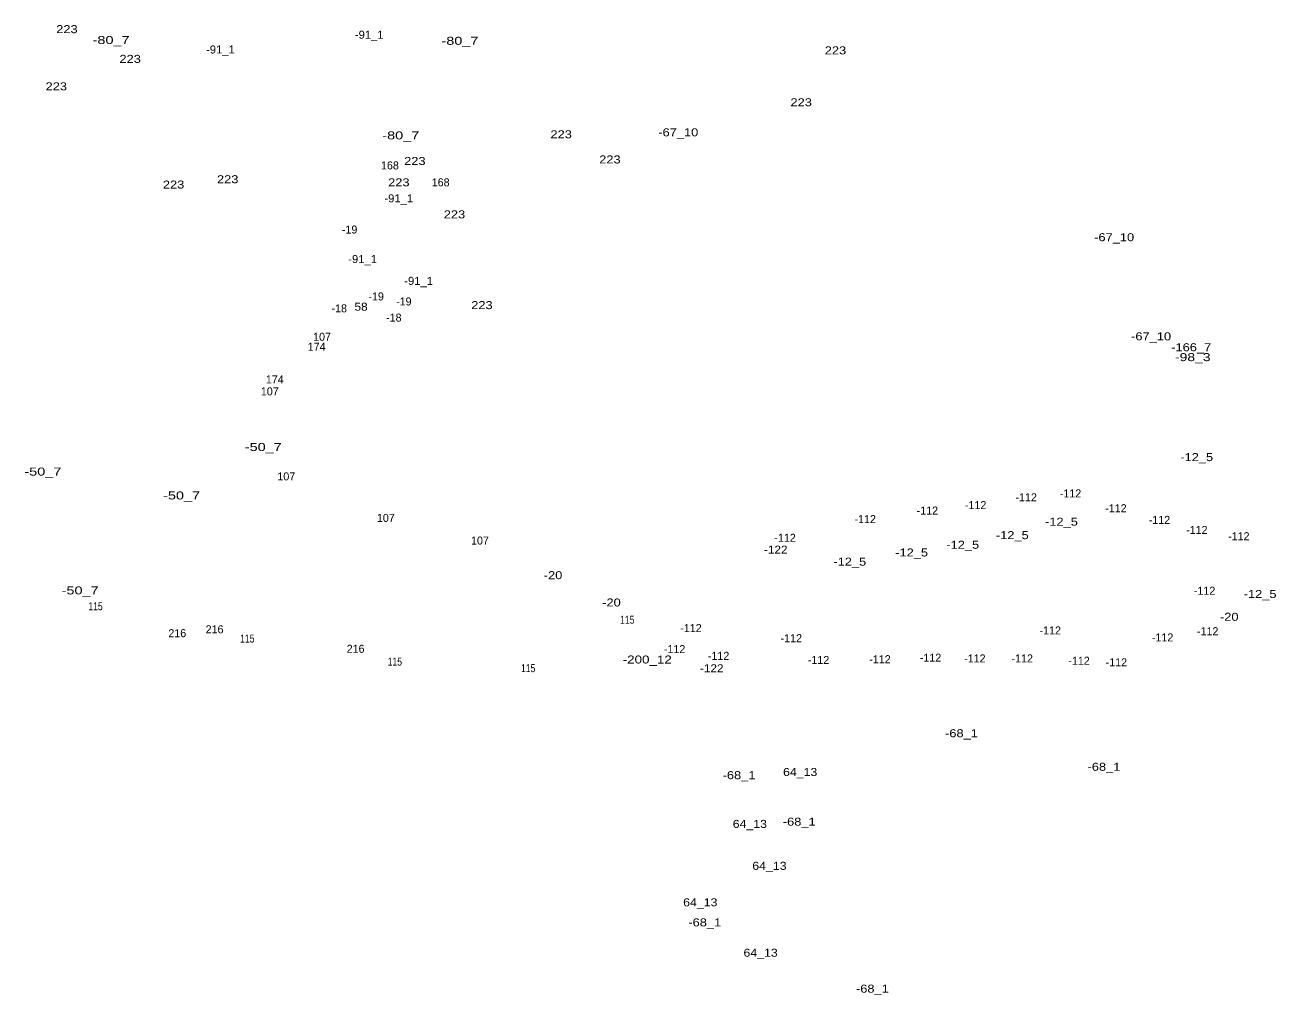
# Model space of a CAD drawing. Extents: x -662996 to -659766, y -998554 to -993949.
# Drawn here: x -662461 to -661836, y -995729 to -995245 of the extents above; entities that cross this region are included whole.
import ezdxf
from ezdxf.enums import TextEntityAlignment as Align

# ---------------------------------------------------------------- set-up
doc = ezdxf.new("R2010")
doc.units = 0
doc.header["$LTSCALE"] = 1.6
doc.layers.add('24', color=7, linetype='Continuous')

msp = doc.modelspace()

# ---------------------------------------------------------------- texts
at = {"layer": '24'}
for s, width, p in [('223', 1.2, (-662440.29, -995248.59)), ('-91_1', 1.05, (-662289.221, -995251.36)), ('-80_7', 1.35, (-662418.22, -995254.02)), ('-91_1', 1.05, (-662363.591, -995258.74)), ('-80_7', 1.35, (-662243.88, -995254.41)), ('223', 1.2, (-662056.199, -995259.2)), ('223', 1.2, (-662408.679, -995263.44)), ('223', 1.2, (-662445.62, -995277.16)), ('223', 1.2, (-662073.34, -995285.11)), ('-80_7', 1.35, (-662273.45, -995301.66)), ('223', 1.2, (-662193.299, -995301.11)), ('-67_10', 1.2, (-662134.77, -995300.13)), ('223', 1.2, (-662266.41, -995314.44)), ('223', 1.2, (-662168.929, -995313.68)), ('223', 1.2, (-662386.98, -995326.22)), ('223', 1.2, (-662359.939, -995323.56)), ('223', 1.2, (-662274.41, -995325.11)), ('-91_1', 1.05, (-662274.451, -995333.1)), ('223', 1.2, (-662246.61, -995341.11)), ('-67_10', 1.2, (-661916.94, -995352.52)), ('-91_1', 1.05, (-662292.52, -995363.43)), ('-91_1', 1.05, (-662264.541, -995374.32)), ('58', 1.1, (-662293.299, -995387.24)), ('223', 1.2, (-662232.9, -995386.44)), ('-67_10', 1.2, (-661898.47, -995402.04)), ('-166_7', 1.2, (-661878.429, -995407.48)), ('-98_3', 1.3, (-661877.65, -995412.42)), ('-50_7', 1.35, (-662342.16, -995457.31)), ('-12_5', 1.2, (-661875.679, -995462.36)), ('-50_7', 1.35, (-662452.32, -995469.6)), ('-50_7', 1.35, (-662383, -995481.51)), ('-12_5', 1.2, (-661943.27, -995494.63)), ('-12_5', 1.2, (-661967.84, -995501.35)), ('-122', 1.1, (-662086.061, -995508.59)), ('-12_5', 1.2, (-661992.61, -995506.15)), ('-12_5', 1.2, (-662049.059, -995514.6)), ('-12_5', 1.2, (-662018.15, -995510)), ('-20', 1.2, (-662197.34, -995521.34)), ('-50_7', 1.35, (-662433.69, -995528.95)), ('-12_5', 1.2, (-661844, -995530.74)), ('115', 0.8, (-662425.99, -995536.86)), ('-20', 1.2, (-662168.15, -995534.98)), ('115', 0.8, (-662160.25, -995543.58)), ('-20', 1.2, (-661859.41, -995542.14)), ('115', 0.8, (-662350.15, -995552.99)), ('115', 0.8, (-662276.41, -995564.52)), ('-200_12', 1.25, (-662150.27, -995563.47)), ('115', 0.8, (-662209.79, -995567.78)), ('-122', 1.1, (-662118.041, -995567.84)), ('-68_1', 1.2, (-661993.24, -995600.29)), ('-68_1', 1.2, (-662104.4, -995621.24)), ('64_13', 1.15, (-662073.85, -995619.66)), ('-68_1', 1.2, (-661922.03, -995617.05)), ('64_13', 1.15, (-662099, -995645.59)), ('-68_1', 1.2, (-662074.321, -995644.48)), ('64_13', 1.15, (-662089.209, -995666.53)), ('64_13', 1.15, (-662123.77, -995684.77)), ('-68_1', 1.2, (-662121.541, -995694.77)), ('64_13', 1.15, (-662093.62, -995709.94)), ('-68_1', 1.2, (-662037.76, -995727.88))]:
    msp.add_text(s, height=4, dxfattribs=dict(at, width=width)).set_placement(p, align=Align.CENTER)
for s, p in [('168', (-662278.861, -995316.66)), ('168', (-662253.51, -995325.11)), ('-19', (-662299.01, -995348.68)), ('-19', (-662285.76, -995382.1)), ('-18', (-662304.191, -995388.06)), ('-19', (-662271.93, -995384.6)), ('-18', (-662276.931, -995392.67)), ('107', (-662312.801, -995402.25)), ('174', (-662315.49, -995407.22)), ('174', (-662336.42, -995423.55)), ('107', (-662338.91, -995429.53)), ('107', (-662330.65, -995471.98)), ('-112', (-661960.91, -995482.44)), ('-112', (-661938.75, -995480.49)), ('-112', (-662010.27, -995489.05)), ('-112', (-661986.171, -995486.33)), ('-112', (-661916.051, -995487.89)), ('107', (-662280.921, -995492.72)), ('-112', (-662041.361, -995493.32)), ('-112', (-661894.291, -995493.72)), ('-112', (-662081.4, -995502.66)), ('-112', (-661875.63, -995498.77)), ('-112', (-661854.64, -995501.88)), ('107', (-662233.88, -995504.05)), ('-112', (-661871.74, -995529.1)), ('216', (-662385.14, -995550.31)), ('216', (-662366.51, -995548.39)), ('-112', (-662128.431, -995547.76)), ('-112', (-662078.291, -995552.81)), ('-112', (-661948.861, -995548.93)), ('-112', (-661892.731, -995552.43)), ('-112', (-661870.191, -995549.32)), ('216', (-662296.02, -995558.11)), ('-112', (-662136.591, -995558.26)), ('-112', (-662114.62, -995561.63)), ('-112', (-662064.681, -995563.7)), ('-112', (-662033.981, -995563.31)), ('-112', (-662008.711, -995562.54)), ('-112', (-661986.561, -995562.92)), ('-112', (-661962.851, -995562.92)), ('-112', (-661934.481, -995564.09)), ('-112', (-661915.821, -995564.87))]:
    msp.add_text(s, height=4, dxfattribs=at).set_placement(p, align=Align.CENTER)

doc.saveas('drawing.dxf')
